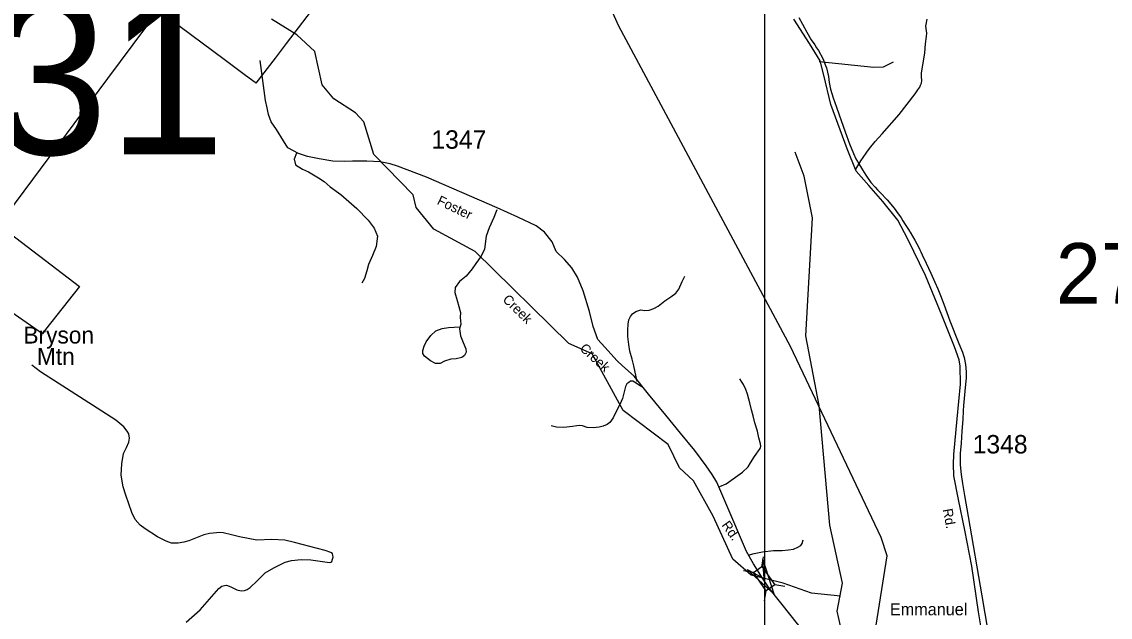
# Model space of a CAD drawing. Extents: x 884530 to 1028605, y 526725 to 653634.
# Drawn here: x 923991 to 931362, y 620795 to 624831 of the extents above; entities that cross this region are included whole.
import ezdxf

# ---------------------------------------------------------------- set-up
doc = ezdxf.new("R2010")
doc.units = 0
for name, color, linetype in [('Exist Boundary Land Use Forest National US Forest Service', 7, 'Continuous'), ('Exist Boundary Political City Limit New', 7, 'Continuous'), ('Exist Cultural Church Label', 7, 'Continuous'), ('Exist Geographical Mountain Summit Label', 7, 'Continuous'), ('Exist Hydrographic Creek Single Shore', 7, 'Continuous'), ('Exist Hydrographic Creek Single Shore Label', 7, 'Continuous'), ('Exist Road Non-System Type 51', 7, 'Continuous'), ('Exist Road Secondary Structure Pipe Number Label', 7, 'Continuous'), ('Exist Road Secondary Structure Standard Bridge Attributed CELL', 7, 'Continuous'), ('Exist Road Secondary Structure Standard Bridge CELL', 7, 'Continuous'), ('Exist Road Secondary Structure Standard Bridge Number Label', 7, 'Continuous'), ('Exist Road Secondary Type 41 Attributed', 7, 'Continuous'), ('Exist Road Secondary Type 51 Attributed', 7, 'Continuous'), ('Exist Road Secondary Type 51 Label', 7, 'Continuous'), ('Exist Road Secondary Type 51 Number Label', 7, 'Continuous'), ('Exist Utilities Electrical Transmission Line', 7, 'Continuous'), ('Map Preparation Boundary City Limit Buffer Line', 7, 'Continuous'), ('Map Preparation Inset Cut Line', 7, 'Continuous')]:
    doc.layers.add(name, color=color, linetype=linetype)

msp = doc.modelspace()

# ---------------------------------------------------------------- linework, layer by layer
at = {"layer": 'Exist Boundary Land Use Forest National US Forest Service'}
msp.add_lwpolyline([(926386.9, 625477.1), (925781.4, 624682.8), (925706.3, 624584.1), (925577, 624414.6), (925572.2, 624418.2), (925506.5, 624467.1), (925360.9, 624575.6), (924915.1, 624907.8), (924572.4, 624447.3), (923832.6, 623453.6), (924382.9, 623037.8), (924152.5, 622744.8), (924131.7, 622716.3), (923536.8, 623126.4), (923234.3, 623350.9), (923584, 624281.9), (923881, 624708.4), (923630, 624753.9), (923575.3, 624877.5)], dxfattribs=at)
at = {"layer": 'Exist Boundary Political City Limit New'}
for points in [[(929253.8, 624859.2), (929277.1, 624814.1), (929306.6, 624760.2), (929337.4, 624709.2), (929360.9, 624674.7), (929373.7, 624655.2), (929386.6, 624635.5), (929415.1, 624582.8), (929433.8, 624533.9), (929440.1, 624517.6), (929453.1, 624460.1), (929457.7, 624419.6), (929467, 624374), (929485.8, 624314.7), (929507.8, 624252.7), (929526.3, 624199.9), (929566.8, 624084.2), (929596.4, 624002.8), (929622.2, 623938.2), (929639.5, 623903.1), (929650.1, 623883.7), (929653.4, 623878.4), (929684.1, 623828.4), (929706.8, 623792), (929741.5, 623742.4), (929770.1, 623709.6), (929786.5, 623692.8), (929804.4, 623674.4), (929850.1, 623624.7), (929898.4, 623566.8), (929926.6, 623529.4), (929934.8, 623518.4), (929945.1, 623502.3), (929957.8, 623482.5), (929973.6, 623456.4), (929978.1, 623449.1), (930000, 623415.6)], [(930000, 623415.6), (930001.1, 623413.9), (930007.6, 623403.9), (930039.3, 623349.8), (930065.3, 623301.1), (930072.5, 623286.1), (930079.3, 623271.9), (930088.9, 623251.9), (930115.7, 623194.9), (930147.4, 623126), (930174.9, 623065.8), (930194.8, 623021.4), (930212.8, 622976.8), (930235.2, 622916.2), (930275.6, 622805.1), (930293, 622758.7), (930313.1, 622707.2), (930330.9, 622662.4), (930347.4, 622622.4), (930361.5, 622591.7), (930369.1, 622568.9), (930373.3, 622556.1), (930381.7, 622508.3), (930385.9, 622458.6), (930385.8, 622415.6), (930382.6, 622374.2), (930377.9, 622328.2), (930372.9, 622276.7), (930368.8, 622229.8), (930366.3, 622195.1), (930362.9, 622135.8), (930357.8, 622055.9), (930351.5, 621974.5), (930347.2, 621927), (930346.1, 621906.8), (930344.7, 621880.4), (930344.7, 621879.2), (930344.8, 621877.9), (930345.3, 621853.5), (930345.9, 621828.2), (930352.6, 621761.6), (930361.2, 621702.1), (930375.2, 621620.2), (930399.1, 621477.6), (930491.6, 620940.2), (930574.2, 620461)]]:
    msp.add_lwpolyline(points, dxfattribs=at)
at = {"layer": 'Exist Hydrographic Creek Single Shore'}
for points in [[(929534.5, 620938), (929338.9, 620958.8), (929147.5, 621025.3), (928930.6, 621081.4), (928805.9, 621189.8), (928672.2, 621480.1), (928538.9, 621719), (928445.2, 621807.4), (928367.6, 621966.5), (928063.2, 622197.2), (927852.5, 622579.5), (927696.6, 622651.5), (927060.2, 623274.6), (926782.2, 623424.6), (926662.3, 623571.4), (926640.4, 623657.1), (926375, 623931.6), (926307.8, 624152.8), (926251.6, 624212.9), (926105, 624307.7), (926025.2, 624404.6), (925974.7, 624628.7), (925853.7, 624742.7), (925682.5, 624847.9)], [(929548.1, 621026.1), (929461.9, 621418.3), (929391.1, 622230.3), (929299.6, 622701.4), (929344.8, 623501.2), (929288.4, 623784.5), (929227.3, 623946.5)], [(929790, 620481.1), (929733, 620582.2), (929614.5, 620677.1), (929534.5, 620736.4), (929513.7, 620837.2), (929548.1, 621026.1)]]:
    msp.add_lwpolyline(points, dxfattribs=at)
at = {"layer": 'Exist Road Non-System Type 51'}
for points in [[(929638.8, 623832.6), (929672.7, 623889.3), (929688.6, 623911.9), (929713.5, 623948.1), (929731.7, 623973.1), (929770.2, 624018.4), (929817.8, 624070.4), (929933.2, 624201.9), (930039.7, 624342.3), (930057.8, 624369.4), (930071.4, 624387.5), (930076, 624401.2), (930082.7, 624414.8), (930085, 624432.9), (930082.7, 624457.8), (930084.2, 624483.1), (930106.5, 624619.5), (930111.5, 624681.5), (930116.5, 624731.1), (930118.9, 624753.5), (930113.9, 624800.6), (930121.4, 624847.6)], [(925715.1, 624100.2), (925680.3, 624153.2), (925662.4, 624202.1), (925652.6, 624247.1), (925641.6, 624297.6), (925604.3, 624567.9)], [(929391.3, 624561.2), (929761.8, 624522.8), (929826.3, 624525.3), (929893.3, 624560)], [(925850.8, 623940.8), (925834.8, 623900.3), (925845.1, 623860.8), (925892.2, 623832.6), (925931.6, 623814.6), (926000.9, 623774.2), (926037.7, 623748.8), (926079.9, 623711.1), (926151.5, 623659.3), (926260.5, 623565.5), (926337.3, 623486.2), (926377, 623431.6), (926399.4, 623377), (926391.9, 623307.6), (926365.3, 623247.8), (926339.9, 623186.1), (926327.4, 623143.2), (926310.9, 623089.9), (926292.7, 623059.7)], [(927207.3, 623556.8), (927187.2, 623504.9), (927156.9, 623433.6), (927135.8, 623377), (927123.4, 623290.3), (927101.2, 623243.2), (927066.4, 623193.6), (927041.6, 623156.4), (926999.5, 623106.8), (926954.9, 623069.6), (926925, 623029.9), (926922.6, 622995.2), (926939, 622941.9), (926961.8, 622860.4), (926959.8, 622826.6), (926964.3, 622781.8), (926956.3, 622749.3), (926962.2, 622702.4), (926980.7, 622656.2), (926998.9, 622614.2), (927000.4, 622592), (926989.2, 622569.8), (926971.2, 622554.4), (926933.6, 622546.1), (926896.1, 622544.7), (926853.2, 622531.5), (926823.4, 622514.1), (926793.6, 622514.1), (926758.9, 622534), (926719.3, 622563.8), (926706.8, 622583.5), (926706.8, 622603.4), (926716.8, 622633.2), (926729.4, 622662.8), (926762.1, 622704.8), (926795.8, 622735.7), (926838, 622752.1), (926881.2, 622758.1), (926956.5, 622763.1)], [(928158.1, 622393.8), (928136.8, 622498.4), (928124.5, 622544.6), (928108.2, 622597.8), (928101, 622644.3), (928095.5, 622697.7), (928095.8, 622741.4), (928096.8, 622782.4), (928101.9, 622811), (928112.3, 622833.6), (928126.5, 622851.1), (928149.1, 622866.4), (928183.9, 622877.7), (928209.6, 622874.6), (928239.3, 622876.7), (928271.1, 622888), (928299.8, 622903.4), (928345.9, 622940.2), (928385.9, 622966.9), (928420.8, 622992.6), (928441.3, 623018.2), (928462.8, 623070.4), (928480.2, 623107.3)], [(925105, 620761.8), (925198.9, 620844.3), (925325.9, 620990.7), (925346.2, 621005.9), (925363.7, 621011), (925378.2, 621011.8), (925405.9, 621002.3), (925446.6, 620980.5), (925476.3, 620973.3), (925498.9, 620975.4), (925517.9, 620984.1), (925537.4, 620997.2), (925584, 621043), (925638.4, 621096), (925697.5, 621129.8), (925775.1, 621168.7), (925817.9, 621179.6), (925881.9, 621187.6), (925948.1, 621184), (926074.5, 621165.1), (926084, 621168.1), (926091, 621173.6), (926096.3, 621188.4), (926099.3, 621202.2), (926098.5, 621216.7), (926095.6, 621224.3), (926090.6, 621230.9), (926083.9, 621234.9), (926045.5, 621247.3), (925836.9, 621301.8), (925772.2, 621317), (925684.3, 621322.1), (925583.2, 621317.8), (925466.2, 621340.3), (925410.9, 621352.6), (925355.7, 621366.5), (925333.2, 621369.3), (925288.1, 621365.7), (925261.2, 621362), (925223.4, 621352.6), (925122.4, 621311.9), (925089.1, 621303.3), (925049.7, 621296.7), (925005.3, 621298.1), (924968.3, 621310.5), (924911.2, 621340.6), (924826.6, 621394), (924793.2, 621418.1), (924759.8, 621457.3), (924736.5, 621506), (924695.1, 621621.5), (924676.8, 621679.7), (924663.1, 621757.9), (924667.5, 621834.7), (924680.6, 621905), (924700.8, 621946.4), (924715.4, 621982.1), (924721.2, 622009.7), (924715.4, 622038), (924705.2, 622056.9), (924682.7, 622085.3), (924627.4, 622130.3), (924501, 622211.7), (924238.6, 622381.8), (924117.2, 622458.8), (924059.8, 622503.9)], [(928190.6, 622357.8), (928167.3, 622369.9), (928152.3, 622381.1), (928140.5, 622388.9), (928128, 622394.2), (928113.1, 622394.4), (928101, 622386.7), (928088.6, 622377.1), (928079.4, 622357.9), (928059.8, 622277.4), (928040.7, 622236.7), (928027, 622211.1), (927996, 622145.5), (927985, 622130), (927973.8, 622116), (927956, 622102.2), (927928.5, 622090.4), (927900.4, 622083.8), (927859.7, 622078.6), (927820.3, 622080.2), (927788.3, 622091.4), (927769.7, 622095.6), (927750.1, 622093), (927719.6, 622088.3), (927661.2, 622080.1), (927611.9, 622083.2), (927576, 622091.4)], [(928717.1, 621680.4), (928760.5, 621699.9), (928871.5, 621778.6), (928909.2, 621814.8), (928924.9, 621840.7), (928953.5, 621884.4), (928990.2, 621938.2), (928994.9, 621955.6), (928994.3, 621971.1), (928982.4, 622011.4), (928973, 622055.4), (928955.7, 622113.7), (928943.6, 622159.7), (928932.8, 622201.7), (928921.8, 622248.2), (928914.7, 622273.4), (928904.5, 622308), (928893.9, 622338.1), (928879.3, 622371.7), (928864.4, 622393.7), (928854.5, 622410.3)], [(928910.9, 621216.1), (928950.1, 621226.3), (929006.7, 621238.9), (929080.7, 621246.8), (929140.5, 621248.3), (929182.2, 621251.5), (929217.6, 621257), (929246.6, 621270.5), (929266.4, 621280.5), (929276.7, 621295.5), (929282.9, 621320.7)]]:
    msp.add_lwpolyline(points, dxfattribs=at)
at = {"layer": 'Exist Road Secondary Structure Standard Bridge Attributed CELL'}
msp.add_lwpolyline([(929009.6, 621186.9), (929083.8, 620954.7), (928903.4, 621118.7), (929017.9, 621057.2)], close=True, dxfattribs=at)
at = {"layer": 'Exist Road Secondary Structure Standard Bridge CELL'}
for p, q in [((929002.3, 621137.5), (929014.2, 621205.5)), ((928945.7, 621097.9), (928877.8, 621109.9)), ((929157.9, 621002.5), (929090, 621014.5)), ((929020.2, 620906), (929032.1, 620974))]:
    msp.add_line(p, q, dxfattribs=at)
msp.add_lwpolyline([(929032.1, 620974), (928945.5, 621097.7), (929003.3, 621138.2), (929090, 621014.5)], close=True, dxfattribs=at)
at = {"layer": 'Exist Road Secondary Type 41 Attributed'}
for points in [[(929007.9, 621060.2), (928945.7, 621157.6), (928899.6, 621239.9), (928758.7, 621567.8), (928697.3, 621709.9), (928665.2, 621761.8), (928625.4, 621821.7), (928548.4, 621924.3), (928452.3, 622043), (928353.4, 622165.8), (928234.5, 622307.3), (928137.7, 622428.2), (928059.5, 622498.5), (928022.1, 622532.4), (927939.9, 622625.9), (927892.6, 622676.6), (927861.1, 622765.7), (927834.5, 622866.6), (927793.3, 623006.6), (927754.5, 623099.2), (927715.9, 623162.8), (927665.3, 623219.8), (927610.2, 623275), (927582, 623340.3), (927531.3, 623405.7), (927475, 623447.4), (927349.4, 623506.7), (927209.8, 623569.8), (926731.5, 623777), (926600.8, 623827.8), (926534.4, 623851.4), (926486, 623867.2), (926417.2, 623882.1), (926327.4, 623885.2), (926230.9, 623887.2), (926174.6, 623885), (926097.4, 623887.2), (926004.5, 623900.9), (925926.4, 623918.2), (925864.9, 623939.1), (925791.7, 623976.3), (925762.4, 624023.6), (925715.1, 624100.2)], [(929345.2, 620622.2), (929201.2, 620804.6), (929053.1, 620991.8), (929007.9, 621060.2)]]:
    msp.add_lwpolyline(points, dxfattribs=at)
at = {"layer": 'Exist Road Secondary Type 51 Attributed'}
msp.add_lwpolyline([(930542, 620397.5), (930470.1, 620832.4), (930425, 621141.1), (930376.4, 621385.3), (930333.7, 621594), (930302, 621753.8), (930299.6, 621833.1), (930303.3, 621897), (930325.2, 622139.8), (930347.1, 622374.5), (930345.9, 622496.5), (930338.6, 622540.4), (930306.9, 622628.3), (930222.1, 622841.8), (930111.1, 623110.3), (929991.6, 623356.7), (929923.5, 623486.2), (929822.3, 623613.1), (929726, 623720.5), (929640.7, 623818.1), (929579.9, 623970), (929470.2, 624269.4), (929422.6, 624468.3), (929398.3, 624567.1), (929325.1, 624684.3), (929218.2, 624848.3)], dxfattribs=at)
at = {"layer": 'Exist Utilities Electrical Transmission Line'}
msp.add_lwpolyline([(919215.5, 597808.3), (921124.3, 600075), (921355.3, 603059.1), (925357.2, 607735.8), (926768.3, 610919.4), (927159.2, 611823.9), (928300.4, 613120.2), (929404.2, 614372.6), (929377.4, 616031), (929346.3, 617714.4), (929345.2, 618021.6), (929852.2, 621210.3), (929810.4, 621334.5), (929197.7, 622629.2), (928034.6, 624800), (927482.4, 626024.4), (927504.2, 627587.8), (927629.3, 629272), (927654.5, 630965.2), (927677.4, 631260.1), (927996.2, 631739.4), (928303.4, 632200.5), (928506, 632490), (928981.9, 633140.2)], dxfattribs=at)
at = {"layer": 'Map Preparation Boundary City Limit Buffer Line'}
for points in [[(929253.8, 624859.2), (929277.1, 624814.1), (929306.6, 624760.2), (929337.4, 624709.2), (929360.9, 624674.7), (929373.7, 624655.2), (929386.6, 624635.5), (929415.1, 624582.8), (929433.8, 624533.9), (929440.1, 624517.6), (929453.1, 624460.1), (929457.7, 624419.6), (929467, 624374), (929485.8, 624314.7), (929507.8, 624252.7), (929526.3, 624199.9), (929566.8, 624084.2), (929596.4, 624002.8), (929622.2, 623938.2), (929639.5, 623903.1), (929650.1, 623883.7), (929653.4, 623878.4), (929684.1, 623828.4), (929706.8, 623792), (929741.5, 623742.4), (929770.1, 623709.6), (929786.5, 623692.8), (929804.4, 623674.4), (929850.1, 623624.7), (929898.4, 623566.8), (929926.6, 623529.4), (929934.8, 623518.4), (929945.1, 623502.3), (929957.8, 623482.5), (929973.6, 623456.4), (929978.1, 623449.1), (930000, 623415.6)], [(930000, 623415.6), (930001.1, 623413.9), (930007.6, 623403.9), (930039.3, 623349.8), (930065.3, 623301.1), (930072.5, 623286.1), (930079.3, 623271.9), (930088.9, 623251.9), (930115.7, 623194.9), (930147.4, 623126), (930174.9, 623065.8), (930194.8, 623021.4), (930212.8, 622976.8), (930235.2, 622916.2), (930275.6, 622805.1), (930293, 622758.7), (930313.1, 622707.2), (930330.9, 622662.4), (930347.4, 622622.4), (930361.5, 622591.7), (930369.1, 622568.9), (930373.3, 622556.1), (930381.7, 622508.3), (930385.9, 622458.6), (930385.8, 622415.6), (930382.6, 622374.2), (930377.9, 622328.2), (930372.9, 622276.7), (930368.8, 622229.8), (930366.3, 622195.1), (930362.9, 622135.8), (930357.8, 622055.9), (930351.5, 621974.5), (930347.2, 621927), (930346.1, 621906.8), (930344.7, 621880.4), (930344.7, 621879.2), (930344.8, 621877.9), (930345.3, 621853.5), (930345.9, 621828.2), (930352.6, 621761.6), (930361.2, 621702.1), (930375.2, 621620.2), (930399.1, 621477.6), (930491.6, 620940.2), (930574.2, 620461)]]:
    msp.add_lwpolyline(points, dxfattribs=at)
at = {"layer": 'Map Preparation Inset Cut Line'}
msp.add_lwpolyline([(929019.7, 608590.9), (973281.3, 608590.9), (973281.3, 635645.7), (929019.7, 635645.7)], close=True, dxfattribs=at)

# ---------------------------------------------------------------- texts
at = {"layer": 'Exist Cultural Church Label'}
msp.add_text('Emmanuel', height=82.02, dxfattribs=at).set_placement((929869.9, 620808.2))
at = {"layer": 'Exist Geographical Mountain Summit Label'}
for s, p in [('Bryson', (924002.3, 622650.2)), ('Mtn', (924093.5, 622505.8))]:
    msp.add_text(s, height=114.83, dxfattribs=at).set_placement(p)
at = {"layer": 'Exist Hydrographic Creek Single Shore Label'}
msp.add_text('Creek', height=65.62, rotation=315.60623, dxfattribs=at).set_placement((927242.7, 622942.7))
msp.add_text('Creek', height=65.62, rotation=315.60623, dxfattribs=at).set_placement((927242.7, 622942.7))
at = {"layer": 'Exist Road Secondary Structure Pipe Number Label'}
msp.add_text('P231', height=1066.27, dxfattribs=at).set_placement((922038.2, 623931.8))
at = {"layer": 'Exist Road Secondary Structure Standard Bridge Number Label'}
msp.add_text('270', height=410.1, dxfattribs=at).set_placement((930993.3, 622920.5))
at = {"layer": 'Exist Road Secondary Type 51 Label'}
for s, rotation, p in [('Foster', 334.17062, (926797.7, 623597.1)), ('Creek', 317.69547, (927764.4, 622609.6)), ('Rd.', 280.19769, (930227.9, 621525.8)), ('Rd.', 305.35083, (928727, 621419.2))]:
    msp.add_text(s, height=65.62, rotation=rotation, dxfattribs=at).set_placement(p)
at = {"layer": 'Exist Road Secondary Type 51 Number Label'}
for s, p in [('1347', (926764.9, 623970.4)), ('1348', (930430.3, 621905.2))]:
    msp.add_text(s, height=125, dxfattribs=at).set_placement(p)

doc.saveas('drawing.dxf')
